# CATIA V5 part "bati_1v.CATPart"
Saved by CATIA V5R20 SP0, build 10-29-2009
Part number: bati_1v
Bounding box of the stored display mesh (mm): x -183.607 to 197.756, y -192.424 to 189.727, z 76.842 to 116.842
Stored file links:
  D:\ecole\thinkmotion\IAO\bati_1v.CATPart
  D:\ecole\thinkmotion\IAO\mecanisme coulisseau.CATProduct
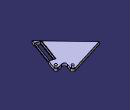
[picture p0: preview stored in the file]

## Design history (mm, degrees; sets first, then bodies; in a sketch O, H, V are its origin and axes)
Set1
  Plane1: linked copy from another document
  Point1 to Point3: linked copy from another document
  Line1: linked copy from another document
  Point4 to Point7: linked copy from another document
  Plane2: linked copy from another document
  Point8: linked copy from another document
  Point9: linked copy from another document
  Plane3: linked copy from another document
  Point10 to Point13: linked copy from another document
  Plane4: linked copy from another document
  Plane5: linked copy from another document
  Point14 to Point17: linked copy from another document
Body1 (main body)
  Sketch1 on Plane1, origin (0, 0, 96.8423), H (1, 0, 0), V (0, -1, 0)
    arc A1 centre (184.3405, -102.0654) radius 13.4164 from (196.9445, -97.4676) to (180.4564, -114.9073) cw
    point P1 (184.3405, -102.0654)
    point P2 (196.9445, -97.4676)
    point P3 (180.4564, -114.9073)
    reference projected point E1 (184.3405, -102.0654) from Point1
    line L1 (180.4564, -114.9073) -> (99.1246, -90.3077)
    point P4 (180.4564, -114.9073)
    point P5 (99.1246, -90.3077)
    reference projected point E2 (99.1246, -90.3077) from Point3
    line L2 (91.195, 192.4238) -> (196.9445, -97.4676)
    point P6 (91.195, 192.4238)
    point P7 (196.9445, -97.4676)
    reference projected point E3 (91.195, 192.4238) from Point4
    reference projected line E4 (283.8049, -335.5783) -> (202.7297, -113.3266) from Line1
    line L3 (99.1246, -90.3077) -> (129.6333, -169.3281)
    point P8 (99.1246, -90.3077)
    point P9 (129.6333, -169.3281)
    reference projected point E5 (99.1246, -90.3077) from Point3
    arc A2 centre (115.6401, -174.7307) radius 15 from (111.2238, -189.0659) to (129.6333, -169.3281) ccw
    point P10 (115.6401, -174.7307)
    point P11 (111.2238, -189.0659)
    point P12 (129.6333, -169.3281)
    reference projected point E6 (115.6401, -174.7307) from Point5
    reference projected point E7 (126.5399, -185.0358) from Point6
    line L4 (111.2238, -189.0659) -> (-183.6069, -98.2374)
    point P13 (111.2238, -189.0659)
    point P14 (-183.6069, -98.2374)
    reference projected point E8 (-183.6069, -98.2374) from Point7
    line L5 (91.195, 192.4238) -> (-183.6069, -98.2374)
    point P15 (91.195, 192.4238)
    point P16 (-183.6069, -98.2374)
    reference projected point E9 (-183.6069, -98.2374) from Point7
    reference projected point E10 (91.195, 192.4238) from Point4
    coincidence: P1 E1, P4 P3, P5 E2, P7 P2, P6 E3, L2 E4, P8 E5, P10 E6, A2 E7, P12 P9, P14 E8, P13 P11, P16 E9, P15 E10, P5 P8, P6 P15, P14 P16
    tangency: A1 L1, L2 A1, L3 A2, A2 L4
  Pad1: profile Sketch1, direction (0, 0, -1), up to Plane2
  Fillet1: radius 20, on edge [face of Pad1 from Sketch1.L1 | face of Pad1 from Sketch1.L3]
  Sketch2 on Plane1, origin (0, 0, 96.8423), H (1, 0, 0), V (0, -1, 0)
    circle A1 centre (184.3405, -102.0654) radius 10
    point P1 (184.3405, -102.0654)
    reference projected point E1 (184.3405, -102.0654) from Point1
    reference projected point E2 (177.4705, -109.332) from Point8
    circle A2 centre (115.6401, -174.7307) radius 10
    point P2 (115.6401, -174.7307)
    reference projected point E3 (115.6401, -174.7307) from Point5
    reference projected point E4 (122.5101, -167.4642) from Point9
    coincidence: P1 E1, A1 E2, P2 E3, A2 E4
  Pad2: profile Sketch2, direction (0, 0, -1), up to Plane3
  Sketch3 on Plane1, origin (0, 0, 96.8423), H (1, 0, 0), V (0, -1, 0)
    point P1 (101.476, 164.2405)
    line L1 (101.476, 164.2405) -> (170.016, -23.6485)
    line L2 (170.016, -23.6485) -> (123.0438, -40.7835)
    line L3 (123.0438, -40.7835) -> (54.5037, 147.1054)
    line L4 (54.5037, 147.1054) -> (101.476, 164.2405)
    point P2 (170.016, -23.6485)
    point P3 (123.0438, -40.7835)
    reference projected point E1 (170.016, -23.6485) from Point10
    reference projected point E2 (101.476, 164.2405) from Point11
    reference projected point E3 (54.5037, 147.1054) from Point12
    reference projected point E4 (123.0438, -40.7835) from Point13
    angle L2 L3 = 90
    coincidence: P2 E1, P1 E2, L4 E3, P3 E4
  Pocket1: profile Sketch3, direction (0, 0, 1), up to Plane1, opposite side up to Plane4
  Pocket2: profile Sketch3, direction (0, 0, 1), up to Plane5, opposite side up to Plane2
  Sketch4 on Plane1, origin (0, 0, 96.8423), H (1, 0, 0), V (0, -1, 0)
    point P1 (92.0815, 160.8134)
    line L1 (92.0815, 160.8134) -> (160.6216, -27.0755)
    line L2 (160.6216, -27.0755) -> (132.4382, -37.3565)
    line L3 (132.4382, -37.3565) -> (63.8982, 150.5324)
    line L4 (63.8982, 150.5324) -> (92.0815, 160.8134)
    point P2 (160.6216, -27.0755)
    point P3 (132.4382, -37.3565)
    point P4 (63.8982, 150.5324)
    reference projected point E1 (160.6216, -27.0755) from Point14
    reference projected point E2 (92.0815, 160.8134) from Point15
    reference projected point E3 (132.4382, -37.3565) from Point16
    reference projected point E4 (63.8982, 150.5324) from Point17
    coincidence: P2 E1, P1 E2, P3 E3, P4 E4
  Pocket3: profile Sketch4, direction (0, 0, 1), up to Plane5, opposite side up to Plane4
